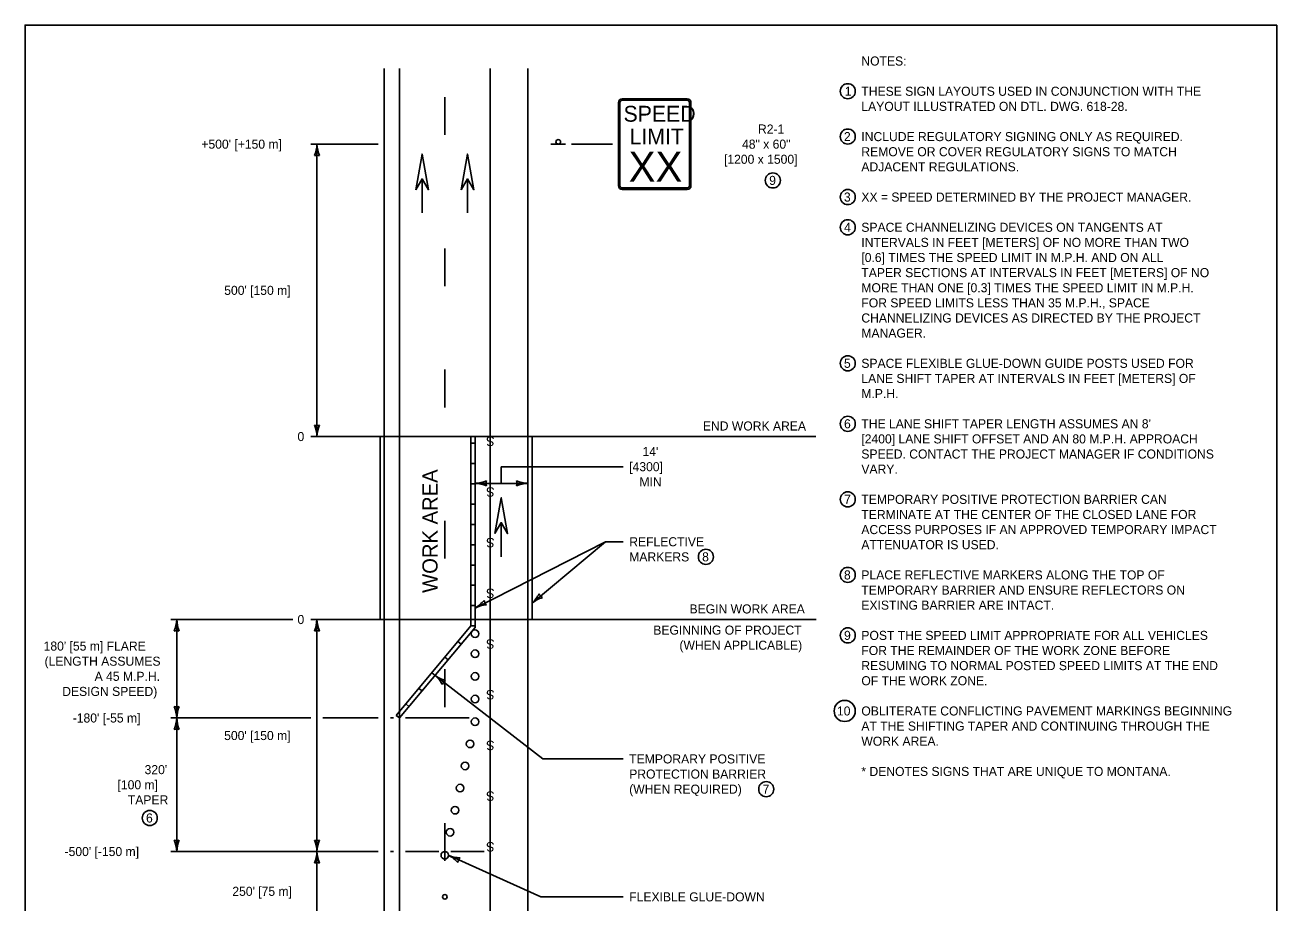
# Model space of a CAD drawing. Extents: x 49991.4 to 50021, y 49987.6 to 50011.4.
# Drawn here: x 50000.34 to 50008.61, y 50005.45 to 50011.26 of the extents above; entities that cross this region are included whole.
import ezdxf

# ---------------------------------------------------------------- set-up
doc = ezdxf.new("R2010")
doc.units = 0
for name, color, linetype in [('Level 1', 7, 'Continuous'), ('Level 2', 7, 'Continuous'), ('Level 3', 7, 'Continuous')]:
    doc.layers.add(name, color=color, linetype=linetype)

msp = doc.modelspace()

# ---------------------------------------------------------------- linework, layer by layer
at = {"layer": 'Level 1'}
for p, q in [((50002.7116, 50002.2097), (50002.7116, 50010.9747)), ((50002.8116, 50002.2097), (50002.8116, 50010.9747)), ((50003.4116, 50002.2102), (50003.4116, 50010.9747)), ((50003.6616, 50002.2101), (50003.6616, 50010.9747)), ((50003.1116, 50010.5353), (50003.1116, 50010.7853)), ((50004.2596, 50010.7497), (50004.2596, 50010.1997)), ((50004.2696, 50010.7497), (50004.2696, 50010.1997)), ((50004.7146, 50010.7747), (50004.2846, 50010.7747)), ((50004.7146, 50010.7647), (50004.2846, 50010.7647)), ((50004.7296, 50010.1997), (50004.7296, 50010.7497)), ((50004.7396, 50010.1997), (50004.7396, 50010.7497)), ((50003.9096, 50010.4747), (50003.8136, 50010.4747)), ((50002.9616, 50010.0192), (50002.9616, 50010.2451)), ((50002.9619, 50010.0192), (50002.9619, 50010.2451)), ((50003.2616, 50010.0192), (50003.2616, 50010.2451)), ((50003.2619, 50010.0192), (50003.2619, 50010.2451)), ((50004.2846, 50010.1847), (50004.7146, 50010.1847)), ((50004.2846, 50010.1747), (50004.7146, 50010.1747)), ((50003.1116, 50009.5353), (50003.1116, 50009.7853)), ((50003.1116, 50008.7329), (50003.1116, 50008.9829)), ((50002.6847, 50007.3297), (50002.6847, 50008.5402)), ((50002.7116, 50008.5402), (50002.6847, 50008.5402)), ((50002.7116, 50007.3297), (50002.7116, 50008.5402)), ((50003.2847, 50007.2871), (50003.2847, 50008.5402)), ((50003.3116, 50008.5402), (50003.2847, 50008.5402)), ((50003.3116, 50008.4967), (50003.2847, 50008.4967)), ((50003.3116, 50007.2871), (50003.3116, 50008.5402)), ((50003.4115, 50008.5402), (50003.4115, 50008.2013)), ((50003.6616, 50007.3297), (50003.6616, 50008.5402)), ((50003.6884, 50008.5402), (50003.6616, 50008.5402)), ((50003.6884, 50007.3297), (50003.6884, 50008.5402)), ((50003.3116, 50008.3623), (50003.2847, 50008.3623)), ((50003.3116, 50008.2279), (50003.2847, 50008.2279)), ((50003.4115, 50008.2013), (50003.4115, 50007.8002)), ((50003.3116, 50008.0935), (50003.2847, 50008.0935)), ((50003.1116, 50007.7329), (50003.1116, 50007.9829)), ((50003.3116, 50007.9591), (50003.2847, 50007.9591)), ((50003.4849, 50007.7447), (50003.4849, 50007.9706)), ((50003.4852, 50007.7447), (50003.4852, 50007.9706)), ((50003.3116, 50007.8247), (50003.2847, 50007.8247)), ((50003.4115, 50007.8002), (50003.4115, 50007.3991)), ((50003.3116, 50007.6903), (50003.2847, 50007.6903)), ((50003.3116, 50007.5559), (50003.2847, 50007.5559)), ((50003.3116, 50007.4215), (50003.2847, 50007.4215)), ((50003.4115, 50007.3991), (50003.4115, 50006.998)), ((50002.7116, 50007.3297), (50002.6847, 50007.3297)), ((50003.6884, 50007.3297), (50003.6616, 50007.3297)), ((50002.7909, 50006.6956), (50003.2847, 50007.2871)), ((50002.8116, 50006.6783), (50003.3116, 50007.2773)), ((50003.3116, 50007.2871), (50003.2847, 50007.2871)), ((50003.3116, 50007.2871), (50003.3116, 50007.2773)), ((50003.2192, 50007.1667), (50003.1986, 50007.1839)), ((50003.1331, 50007.0635), (50003.1124, 50007.0807)), ((50003.1116, 50006.7505), (50003.1116, 50007.0005)), ((50003.4115, 50006.998), (50003.4115, 50006.5969)), ((50003.0469, 50006.9603), (50003.0263, 50006.9775)), ((50002.9608, 50006.8571), (50002.9402, 50006.8744)), ((50002.8747, 50006.754), (50002.8541, 50006.7712)), ((50002.8116, 50006.6783), (50002.7909, 50006.6956)), ((50003.4115, 50006.5969), (50003.4115, 50006.1958)), ((50003.4115, 50006.1958), (50003.4115, 50005.7947)), ((50003.1116, 50005.7329), (50003.1116, 50005.9829))]:
    msp.add_line(p, q, dxfattribs=at)
for points in [[(50008.6146, 50011.2628), (50000.3356, 50011.2628), (50000.3356, 50000.0624), (50008.6146, 50000.0624)], [(50002.9199, 50010.1728), (50002.9616, 50010.4093), (50003.0035, 50010.1728), (50002.9616, 50010.245)], [(50003.2199, 50010.1728), (50003.2616, 50010.4093), (50003.3035, 50010.1728), (50003.2616, 50010.245)], [(50003.4432, 50007.8983), (50003.4849, 50008.1348), (50003.5268, 50007.8983), (50003.4849, 50007.9705)]]:
    msp.add_lwpolyline(points, close=True, dxfattribs=at)
for centre, radius in [((50003.8616, 50010.4899), 0.0152), ((50003.3116, 50007.236), 0.025), ((50003.3116, 50007.1033), 0.025), ((50003.3116, 50006.9533), 0.025), ((50003.3116, 50006.8033), 0.025), ((50003.3116, 50006.6533), 0.025), ((50003.2784, 50006.507), 0.025), ((50003.2453, 50006.3607), 0.025), ((50003.2122, 50006.2144), 0.025), ((50003.1791, 50006.0681), 0.025), ((50003.146, 50005.9218), 0.025), ((50003.1116, 50005.7697), 0.025), ((50003.1116, 50005.4947), 0.015)]:
    msp.add_circle(centre, radius, dxfattribs=at)
for centre, radius, start, end in [((50004.2846, 50010.7497), 0.025, 90, 180), ((50004.2846, 50010.7497), 0.015, 90, 180), ((50004.7146, 50010.7497), 0.025, 0, 90), ((50004.7146, 50010.7497), 0.015, 0, 90), ((50004.2846, 50010.1997), 0.025, 180, 270), ((50004.2846, 50010.1997), 0.015, 180, 270), ((50004.7146, 50010.1997), 0.025, 270, 0), ((50004.7146, 50010.1997), 0.015, 270, 0)]:
    msp.add_arc(centre, radius, start, end, dxfattribs=at)
at = {"layer": 'Level 2'}
for centre, radius in [((50005.7762, 50010.8247), 0.05), ((50005.7762, 50010.5247), 0.05), ((50005.2811, 50010.2347), 0.05), ((50005.7762, 50010.1247), 0.05), ((50005.7762, 50009.9247), 0.05), ((50005.7762, 50009.0247), 0.05), ((50005.7762, 50008.6247), 0.05), ((50005.7762, 50008.1247), 0.05), ((50004.8382, 50007.7441), 0.05), ((50005.7762, 50007.6247), 0.05), ((50005.7762, 50007.2247), 0.05), ((50005.7562, 50006.7247), 0.07), ((50005.2373, 50006.2074), 0.05), ((50001.1603, 50006.0165), 0.05)]:
    msp.add_circle(centre, radius, dxfattribs=at)
at = {"layer": 'Level 3'}
for p, q in [((50002.2262, 50010.4747), (50002.6716, 50010.4747)), ((50002.2662, 50009.3648), (50002.2662, 50010.4747)), ((50003.9496, 50010.4747), (50004.2196, 50010.4747)), ((50002.2662, 50008.5402), (50002.2662, 50009.3648)), ((50002.2262, 50008.5402), (50005.5662, 50008.5402)), ((50004.2911, 50008.3407), (50003.4849, 50008.3407)), ((50003.4849, 50008.2306), (50003.4849, 50008.3407)), ((50003.6616, 50008.2306), (50003.3116, 50008.2306)), ((50003.3116, 50007.4057), (50004.1733, 50007.8442)), ((50003.6884, 50007.4377), (50004.1733, 50007.8442)), ((50004.1733, 50007.8442), (50004.2911, 50007.8442)), ((50001.2989, 50007.3297), (50002.106, 50007.3297)), ((50001.3389, 50006.6783), (50001.3389, 50007.3297)), ((50002.2259, 50007.3297), (50005.5665, 50007.3297)), ((50002.2259, 50007.3297), (50002.6716, 50007.3297)), ((50002.2659, 50007.3297), (50002.2659, 50005.7947)), ((50003.0469, 50006.9603), (50003.7592, 50006.4074)), ((50001.2989, 50006.6783), (50002.2259, 50006.6783)), ((50001.3389, 50006.6783), (50001.3389, 50005.7947)), ((50002.3059, 50006.6783), (50002.6716, 50006.6783)), ((50002.7516, 50006.6783), (50002.7716, 50006.6783)), ((50002.8516, 50006.6783), (50003.2716, 50006.6783)), ((50003.7592, 50006.4074), (50004.2911, 50006.4074)), ((50001.2989, 50005.7947), (50002.6716, 50005.7947)), ((50002.2659, 50005.7947), (50002.2659, 50005.2681)), ((50002.7516, 50005.7947), (50002.7716, 50005.7947)), ((50002.8516, 50005.7947), (50003.0716, 50005.7947)), ((50003.1366, 50005.7697), (50003.7462, 50005.4948)), ((50003.1516, 50005.7947), (50003.3716, 50005.7947)), ((50003.7462, 50005.4948), (50004.2911, 50005.4948))]:
    msp.add_line(p, q, dxfattribs=at)
for centre, radius, start, end in [((50002.044, 50010.4838), 0.2223, 337.45601, 357.63952), ((50002.4989, 50010.4862), 0.233, 182.82731, 202.07716), ((50002.2662, 50010.3465), 0.0548, 72.13882, 107.86118), ((50002.2662, 50008.6684), 0.0548, 252.13882, 287.86118), ((50002.0335, 50008.5287), 0.233, 2.82731, 22.07716), ((50002.4883, 50008.531), 0.2223, 157.45601, 177.63952), ((50003.3024, 50008.4528), 0.2223, 272.36048, 292.54399), ((50003.3001, 50007.9979), 0.233, 67.92284, 87.17269), ((50003.4398, 50008.2306), 0.0548, 162.13882, 197.86118), ((50003.5334, 50008.2306), 0.0548, 342.13882, 17.86118), ((50003.6731, 50008.4634), 0.233, 247.92284, 267.17269), ((50003.6707, 50008.0085), 0.2223, 92.36048, 112.54399), ((50003.527, 50007.6057), 0.233, 313.85734, 333.10719), ((50003.7852, 50007.5219), 0.0548, 203.16885, 238.89121), ((50003.1921, 50007.6058), 0.233, 300.8481, 320.09795), ((50003.4078, 50007.2054), 0.2223, 95.4768, 115.66031), ((50003.4248, 50007.466), 0.0548, 190.15961, 225.88197), ((50003.8274, 50007.2641), 0.2223, 108.48604, 128.66955), ((50001.1168, 50007.3388), 0.2223, 337.45601, 357.63952), ((50001.5716, 50007.3412), 0.233, 182.82731, 202.07716), ((50002.0332, 50007.3412), 0.233, 337.92284, 357.17269), ((50002.488, 50007.3388), 0.2223, 182.36048, 202.54399), ((50001.3389, 50007.2015), 0.0548, 72.13882, 107.86118), ((50002.2659, 50007.2015), 0.0548, 72.13882, 107.86118), ((50003.1792, 50007.139), 0.2223, 233.48191, 253.66542), ((50002.8919, 50006.7864), 0.233, 29.04427, 48.29412), ((50003.1468, 50006.8798), 0.0548, 123.26025, 158.98261), ((50001.1168, 50006.6692), 0.2223, 2.36048, 22.54399), ((50001.3389, 50006.8065), 0.0548, 252.13882, 287.86118), ((50001.5716, 50006.6668), 0.233, 157.92284, 177.17269), ((50001.1062, 50006.6898), 0.233, 337.92284, 357.17269), ((50001.5611, 50006.6875), 0.2223, 182.36048, 202.54399), ((50001.3389, 50006.5501), 0.0548, 72.13882, 107.86118), ((50001.1168, 50005.7855), 0.2223, 2.36048, 22.54399), ((50001.3389, 50005.9229), 0.0548, 252.13882, 287.86118), ((50001.5716, 50005.7832), 0.233, 157.92284, 177.17269), ((50002.0438, 50005.7855), 0.2223, 2.36048, 22.54399), ((50002.2659, 50005.9229), 0.0548, 252.13882, 287.86118), ((50002.4986, 50005.7832), 0.233, 157.92284, 177.17269), ((50002.0438, 50005.8038), 0.2223, 337.45601, 357.63952), ((50002.4986, 50005.8062), 0.233, 182.82731, 202.07716), ((50003.2233, 50005.9744), 0.2223, 247.03674, 267.22025), ((50003.0266, 50005.5642), 0.233, 42.5991, 61.84895), ((50003.2525, 50005.7148), 0.0548, 136.81508, 172.53744), ((50002.2659, 50005.6665), 0.0548, 72.13882, 107.86118)]:
    msp.add_arc(centre, radius, start, end, dxfattribs=at)

# ---------------------------------------------------------------- texts
at = {"layer": 'Level 1'}
for s, height, p in [('SPEED', 0.10512, (50004.2936, 50010.6231)), ('LIMIT', 0.10512, (50004.3334, 50010.473)), ('XX', 0.19892, (50004.3275, 50010.2257))]:
    msp.add_text(s, height=height, dxfattribs=at).set_placement(p)
for p in [(50003.4404, 50008.5399), (50003.4405, 50008.205), (50003.4405, 50007.8696), (50003.4405, 50007.5342), (50003.4405, 50007.1988), (50003.4405, 50006.8634), (50003.4405, 50006.528), (50003.4405, 50006.1926), (50003.4405, 50005.8572)]:
    msp.add_text('S', height=0.0625, rotation=180, dxfattribs=at).set_placement(p)
at = {"layer": 'Level 2'}
for s, p in [('NOTES:', (50005.8662, 50010.9947)), ('1', (50005.7565, 50010.7947)), ('THESE SIGN LAYOUTS USED IN CONJUNCTION WITH THE ', (50005.8662, 50010.7947)), ('LAYOUT ILLUSTRATED ON DTL. DWG. 618-28.', (50005.8662, 50010.6947)), ('R2-1', (50005.1827, 50010.5447)), ('2', (50005.7511, 50010.4947)), ('INCLUDE REGULATORY SIGNING ONLY AS REQUIRED.  ', (50005.8662, 50010.4947)), ("+500' [+150 m]", (50001.5016, 50010.4447)), ('48" x 60"', (50005.0771, 50010.4447)), ('[1200 x 1500]', (50004.9577, 50010.3447)), ('REMOVE OR COVER REGULATORY SIGNS TO MATCH ', (50005.8662, 50010.3947)), ('ADJACENT REGULATIONS.', (50005.8662, 50010.2947)), ('9', (50005.2566, 50010.2047)), ('3', (50005.751, 50010.0947)), ('XX = SPEED DETERMINED BY THE PROJECT MANAGER.', (50005.8662, 50010.0947)), ('4', (50005.7523, 50009.8947)), ('SPACE CHANNELIZING DEVICES ON TANGENTS AT ', (50005.8662, 50009.8947)), ('INTERVALS IN FEET [METERS] OF NO MORE THAN TWO ', (50005.8662, 50009.7947)), ('[0.6] TIMES THE SPEED LIMIT IN M.P.H. AND ON ALL ', (50005.8662, 50009.6947)), ('TAPER SECTIONS AT INTERVALS IN FEET [METERS] OF NO ', (50005.8662, 50009.5947)), ('MORE THAN ONE [0.3] TIMES THE SPEED LIMIT IN M.P.H. ', (50005.8662, 50009.4947)), ("500' [150 m]", (50001.6528, 50009.4774)), ('FOR SPEED LIMITS LESS THAN 35 M.P.H., SPACE ', (50005.8662, 50009.3947)), ('CHANNELIZING DEVICES AS DIRECTED BY THE PROJECT ', (50005.8662, 50009.2947)), ('MANAGER. ', (50005.8662, 50009.1947)), ('5', (50005.7513, 50008.9947)), ('SPACE FLEXIBLE GLUE-DOWN GUIDE POSTS USED FOR ', (50005.8662, 50008.9947)), ('LANE SHIFT TAPER AT INTERVALS IN FEET [METERS] OF ', (50005.8662, 50008.8947)), ('M.P.H.', (50005.8662, 50008.7947)), ('END WORK AREA', (50004.8181, 50008.5802)), ('6', (50005.7517, 50008.5947)), ("THE LANE SHIFT TAPER LENGTH ASSUMES AN 8' ", (50005.8662, 50008.5947)), ('0', (50002.1374, 50008.5102)), ('[2400] LANE SHIFT OFFSET AND AN 80 M.P.H. APPROACH ', (50005.8662, 50008.4947)), ("14'", (50004.4188, 50008.4107)), ('SPEED. CONTACT THE PROJECT MANAGER IF CONDITIONS ', (50005.8662, 50008.3947)), ('[4300]', (50004.3311, 50008.3107)), ('VARY.', (50005.8662, 50008.2947)), ('MIN', (50004.3986, 50008.2107)), ('7', (50005.7524, 50008.0947)), ('TEMPORARY POSITIVE PROTECTION BARRIER CAN ', (50005.8662, 50008.0947)), ('TERMINATE AT THE CENTER OF THE CLOSED LANE FOR ', (50005.8662, 50007.9947)), ('ACCESS PURPOSES IF AN APPROVED TEMPORARY IMPACT ', (50005.8662, 50007.8947)), ('REFLECTIVE', (50004.3311, 50007.8141)), ('ATTENUATOR IS USED.', (50005.8662, 50007.7947)), ('MARKERS', (50004.3311, 50007.7141)), ('8', (50004.8132, 50007.7144)), ('8', (50005.7513, 50007.5947)), ('PLACE REFLECTIVE MARKERS ALONG THE TOP OF ', (50005.8662, 50007.5947)), ('TEMPORARY BARRIER AND ENSURE REFLECTORS ON ', (50005.8662, 50007.4947)), ('BEGIN WORK AREA', (50004.7298, 50007.3697)), ('EXISTING BARRIER ARE INTACT.', (50005.8662, 50007.3947)), ('0', (50002.1373, 50007.2997)), ('BEGINNING OF PROJECT', (50004.4902, 50007.2297)), ('9', (50005.7517, 50007.1947)), ('POST THE SPEED LIMIT APPROPRIATE FOR ALL VEHICLES ', (50005.8662, 50007.1947)), ("180' [55 m] FLARE", (50000.4585, 50007.124)), ('(WHEN APPLICABLE)', (50004.6632, 50007.1297)), ('FOR THE REMAINDER OF THE WORK ZONE BEFORE ', (50005.8662, 50007.0947)), ('(LENGTH ASSUMES', (50000.4648, 50007.024)), ('A 45 M.P.H.', (50000.7958, 50006.924)), ('RESUMING TO NORMAL POSTED SPEED LIMITS AT THE END ', (50005.8662, 50006.9947)), ('OF THE WORK ZONE.', (50005.8662, 50006.8947)), ('DESIGN SPEED)', (50000.5815, 50006.824)), ('10', (50005.7049, 50006.6947)), ('OBLITERATE CONFLICTING PAVEMENT MARKINGS BEGINNING ', (50005.8662, 50006.6947)), ("-180' [-55 m]", (50000.6509, 50006.6483)), ('AT THE SHIFTING TAPER AND CONTINUING THROUGH THE ', (50005.8662, 50006.5947)), ("500' [150 m]", (50001.6525, 50006.5322)), ('WORK AREA.', (50005.8662, 50006.4947)), ('TEMPORARY POSITIVE', (50004.3311, 50006.3774)), ("320' ", (50001.1262, 50006.3065)), ('PROTECTION BARRIER', (50004.3311, 50006.2774)), ('* DENOTES SIGNS THAT ARE UNIQUE TO MONTANA.', (50005.8662, 50006.2947)), ('[100 m]', (50000.9473, 50006.2065)), ('(WHEN REQUIRED)', (50004.3311, 50006.1774)), ('7', (50005.2135, 50006.1777)), ('TAPER', (50001.0155, 50006.1065)), ('6', (50001.1357, 50005.9867)), ("-500' [-150 m]", (50000.597, 50005.7647)), ("250' [75 m]", (50001.7064, 50005.5014)), ('FLEXIBLE GLUE-DOWN', (50004.3311, 50005.4648))]:
    msp.add_text(s, height=0.06, dxfattribs=at).set_placement(p)
msp.add_text('WORK AREA', height=0.1, rotation=90, dxfattribs=at).set_placement((50003.0634, 50007.5057))

doc.saveas('drawing.dxf')
